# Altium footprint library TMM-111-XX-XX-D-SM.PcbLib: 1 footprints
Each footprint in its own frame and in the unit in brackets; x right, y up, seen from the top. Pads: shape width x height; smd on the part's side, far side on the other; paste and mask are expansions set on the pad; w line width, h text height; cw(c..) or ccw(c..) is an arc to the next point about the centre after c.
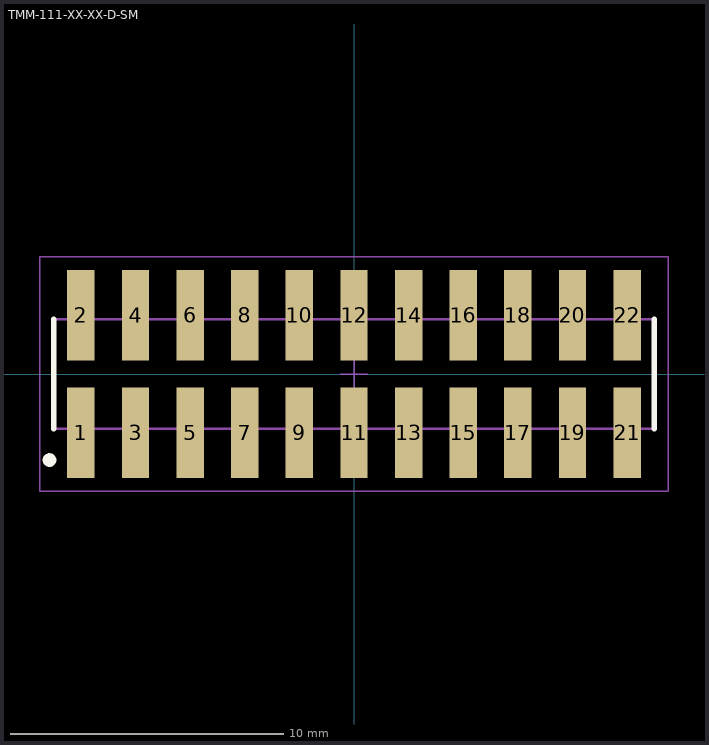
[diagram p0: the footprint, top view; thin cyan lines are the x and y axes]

## TMM-111-XX-XX-D-SM [mm] "2.00mm pitch, 22 pin, terminal strip; double row, SMT"
height 2.77
pads (22):
  rect 1x3.3 smd mask+0: 1(-10,-2.15) 2(-10,2.15) 3(-8,-2.15) 4(-8,2.15) 5(-6,-2.15) 6(-6,2.15) 7(-4,-2.15) 8(-4,2.15) 9(-2,-2.15) 10(-2,2.15) 11(0,-2.15) 12(0,2.15) 13(2,-2.15) 14(2,2.15) 15(4,-2.15) 16(4,2.15) 17(6,-2.15) 18(6,2.15) 19(8,-2.15) 20(8,2.15) 21(10,-2.15) 22(10,2.15)
Top Overlay:
  circle w0.25: c-11.15,-3.15 r0.125
  lines w0.2: -11,-2 -11,2 ; 11,-2 11,2
Mechanical 12:
  lines w0.001: -11,-2 -11,2 11,2 11,-2 -11,-2
Mechanical 13:
  lines w0.1: -11,-2 -11,2 11,2 11,-2 -11,-2
  text ".Designator" at 0,-0.127 h1.52
Mechanical 15:
  lines w0.05: -0.5,0 0.5,0 ; 0,-0.5 0,0.5 ; -11.5,-4.3 -11.5,4.3 11.5,4.3 11.5,-4.3 -11.5,-4.3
